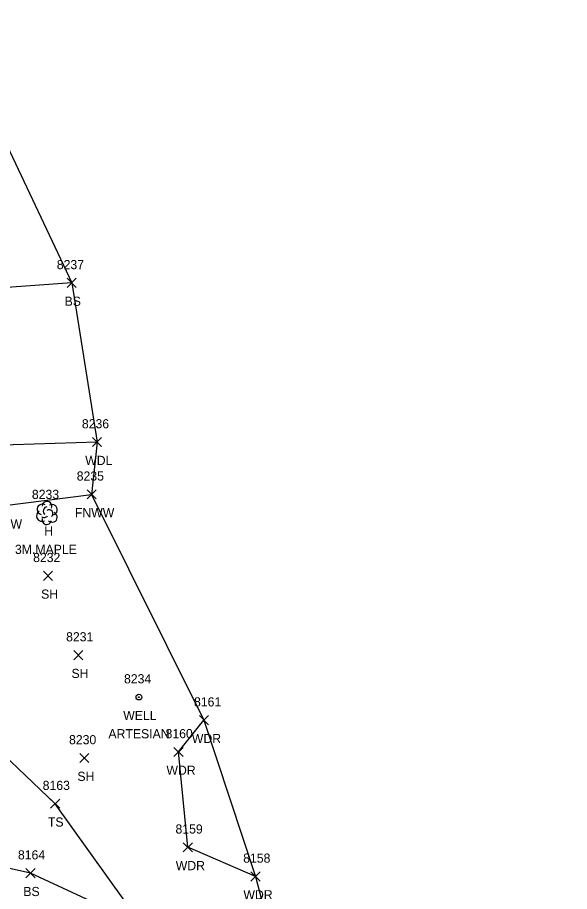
# Model space of a CAD drawing. Extents: x 1439173 to 1457902, y 641926 to 659889.
# Drawn here: x 1448565.9 to 1448686.5, y 645042.9 to 645233.8 of the extents above; entities that cross this region are included whole.
import ezdxf

# ---------------------------------------------------------------- set-up
doc = ezdxf.new("R2010")
doc.units = 0
for name, color, linetype in [('L_A', 7, 'Continuous'), ('L_C', 7, 'Continuous'), ('L_I', 7, 'Continuous'), ('L_TIC', 7, 'Continuous'), ('LAWA', 7, 'Continuous'), ('LELB', 7, 'Continuous'), ('LFNC', 7, 'Continuous'), ('LSOGP', 7, 'Continuous'), ('LTD', 7, 'Continuous'), ('U_A', 7, 'Continuous'), ('U_C', 7, 'Continuous'), ('U_I', 7, 'Continuous'), ('UWW', 7, 'Continuous')]:
    doc.layers.add(name, color=color, linetype=linetype)

msp = doc.modelspace()

# ---------------------------------------------------------------- linework, layer by layer
at = {"layer": 'L_TIC'}
for points in [[(1448576.72, 645174.8), (1448578.72, 645176.8)], [(1448578.72, 645174.8), (1448576.72, 645176.8)], [(1448582.25, 645140.04), (1448584.25, 645142.04)], [(1448584.25, 645140.04), (1448582.25, 645142.04)], [(1448581.06, 645128.63), (1448583.06, 645130.63)], [(1448583.06, 645128.63), (1448581.06, 645130.63)], [(1448571.54, 645110.84), (1448573.54, 645112.84)], [(1448573.54, 645110.84), (1448571.54, 645112.84)], [(1448578.18, 645093.52), (1448580.18, 645095.52)], [(1448580.18, 645093.52), (1448578.18, 645095.52)], [(1448605.62, 645079.31), (1448607.62, 645081.31)], [(1448607.62, 645079.31), (1448605.62, 645081.31)], [(1448600.06, 645072.38), (1448602.06, 645074.38)], [(1448602.06, 645072.38), (1448600.06, 645074.38)], [(1448579.47, 645071.05), (1448581.47, 645073.05)], [(1448581.47, 645071.05), (1448579.47, 645073.05)], [(1448573.11, 645061.07), (1448575.11, 645063.07)], [(1448575.11, 645061.07), (1448573.11, 645063.07)], [(1448602.1, 645051.55), (1448604.1, 645053.55)], [(1448604.1, 645051.55), (1448602.1, 645053.55)], [(1448567.7, 645045.9), (1448569.7, 645047.9)], [(1448569.7, 645045.9), (1448567.7, 645047.9)], [(1448616.89, 645045.19), (1448618.89, 645047.19)], [(1448618.89, 645045.19), (1448616.89, 645047.19)]]:
    msp.add_lwpolyline(points, dxfattribs=at)
at = {"layer": 'LAWA'}
for points in [[(1448583.25, 645141.04), (1448555.69, 645140.17), (1448535.48, 645132.55), (1448519, 645133.93), (1448492.31, 645128.33), (1448482.3, 645125.81)], [(1448617.89, 645046.19), (1448603.1, 645052.55), (1448601.06, 645073.38), (1448606.62, 645080.31)]]:
    msp.add_lwpolyline(points, dxfattribs=at)
at = {"layer": 'LELB'}
for points in [[(1448577.72, 645175.8), (1448560.49, 645174.59), (1448536.53, 645162.43), (1448516.1, 645157.85), (1448496.21, 645148.74), (1448492.31, 645128.33)], [(1448588.4, 644964.73), (1448595.68, 644961.96), (1448604.82, 644963.47), (1448618.68, 644967.85), (1448628.53, 644979.22), (1448629.36, 645002.38), (1448616.76, 645023.59), (1448593.05, 645035.65), (1448568.7, 645046.9), (1448540.01, 645053.31), (1448516.45, 645091.79), (1448498.06, 645114.77)], [(1448590.6, 644967.28), (1448596.82, 644967.58), (1448613.85, 644972.94), (1448616.33, 644980.14), (1448615.51, 645001.09), (1448609.75, 645021.97), (1448593.05, 645035.65), (1448574.11, 645062.07), (1448559.42, 645075.93), (1448549.48, 645094.5)]]:
    msp.add_lwpolyline(points, dxfattribs=at)
at = {"layer": 'LFNC'}
msp.add_lwpolyline([(1448562.52, 645127.15), (1448582.06, 645129.63)], dxfattribs=at)
at = {"layer": 'LSOGP'}
msp.add_lwpolyline([(1448560.06, 645236.66), (1448562.93, 645207.1), (1448577.72, 645175.79), (1448583.25, 645141.04), (1448582.06, 645129.63), (1448606.61, 645080.31), (1448617.88, 645046.19), (1448629.35, 645002.38), (1448628.52, 644979.22), (1448632.94, 644935.46), (1448636.57, 644922.64), (1448639.95, 644901.51), (1448684.15, 644844.88), (1448682.65, 644798.84), (1448683.68, 644767.35), (1448686.54, 644739.65)], dxfattribs=at)
at = {"layer": 'LTD'}
msp.add_line((1448572.27, 645125.62), (1448572.27, 645125.62), dxfattribs=at)
msp.add_line((1448572.27, 645125.62), (1448572.27, 645125.62), dxfattribs=at)
msp.add_arc((1448572.31, 645127.05), 1.05, 335.5272, 180.9563, dxfattribs=at)
for centre, major_axis, ratio, start_param, end_param in [((1448571.47, 645126.29), (1.21, -0.51), 0.895232, 1.570796, 4.712389), ((1448573.31, 645126.2), (-1.14, -0.48), 0.949671, 1.570796, 4.712389), ((1448571.18, 645124.91), (0.58, -1.04), 0.959034, 3.141593, 6.283185), ((1448572.06, 645126.08), (-0.208, -0.792), 0.645439, 3.141593, 6.283185), ((1448572.77, 645125.45), (-0.5, 0.667), 0.989748, 3.141593, 6.283185), ((1448573.27, 645124.79), (-1.09, 0.79), 0.841452, 1.570796, 4.712389), ((1448572.27, 645124.12), (0.26, 1.06), 0.942809, 1.570796, 4.712389), ((1448571.81, 645124.87), (-0.625, -0.083), 0.423636, 0, 3.141593)]:
    msp.add_ellipse(centre, major_axis=major_axis, ratio=ratio, start_param=start_param, end_param=end_param, dxfattribs=at)
at = {"layer": 'UWW'}
for radius in [0.625, 0.0833]:
    msp.add_circle((1448592.41, 645085.35), radius, dxfattribs=at)

# ---------------------------------------------------------------- texts
at = {"layer": 'L_A'}
for s, p in [('BS', (1448576.16, 645170.8)), ('WDL', (1448580.67, 645136.04)), ('FNWW', (1448578.41, 645124.63)), ('FNBW', (1448558.99, 645122.15)), ('H', (1448571.7, 645120.62)), ('SH', (1448571.03, 645106.84)), ('SH', (1448577.67, 645089.52)), ('WDR', (1448603.98, 645075.31)), ('WDR', (1448598.42, 645068.38)), ('SH', (1448578.96, 645067.05)), ('TS', (1448572.52, 645057.07)), ('WDR', (1448600.46, 645047.55)), ('BS', (1448567.14, 645041.9)), ('WDR', (1448615.25, 645041.19))]:
    msp.add_text(s, height=2, dxfattribs=at).set_placement(p)
at = {"layer": 'L_C'}
msp.add_text('3M.MAPLE', height=2, dxfattribs=at).set_placement((1448565.31, 645116.62))
at = {"layer": 'L_I'}
for s, p in [('8237', (1448574.46, 645178.8)), ('8236', (1448579.94, 645144.04)), ('8235', (1448578.81, 645132.63)), ('8233', (1448569.01, 645128.62)), ('8232', (1448569.28, 645114.84)), ('8231', (1448576.49, 645097.52)), ('8161', (1448604.45, 645083.31)), ('8160', (1448598.23, 645076.38)), ('8230', (1448577.13, 645075.05)), ('8163', (1448571.37, 645065.07)), ('8159', (1448600.4, 645055.55)), ('8164', (1448565.96, 645049.9)), ('8158', (1448615.2, 645049.19))]:
    msp.add_text(s, height=2, dxfattribs=at).set_placement(p)
at = {"layer": 'U_A'}
msp.add_text('WELL', height=2, dxfattribs=at).set_placement((1448588.98, 645080.35))
at = {"layer": 'U_C'}
msp.add_text('ARTESIAN', height=2, dxfattribs=at).set_placement((1448585.74, 645076.35))
at = {"layer": 'U_I'}
msp.add_text('8234', height=2, dxfattribs=at).set_placement((1448589.15, 645088.35))

doc.saveas('drawing.dxf')
